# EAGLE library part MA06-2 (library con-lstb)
PIN HEADER
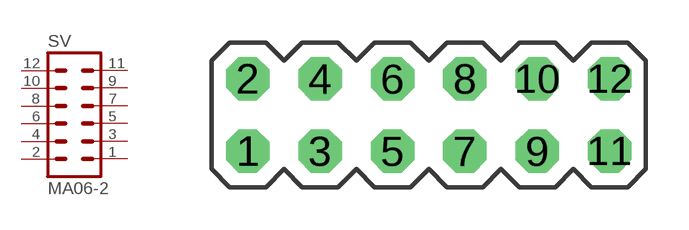
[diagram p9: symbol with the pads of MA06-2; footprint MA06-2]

Designator prefix SV

## MA06-2 (OC_FARNELL: unknown; OC_NEWARK: unknown)  [MA06-2]
1  1  pas
2  2  pas
3  3  pas
4  4  pas
5  5  pas
6  6  pas
7  7  pas
8  8  pas
9  9  pas
10  10  pas
11  11  pas
12  12  pas

## Footprint MA06-2 (pad centres in mm)
PIN HEADER
drill 1.016 octagon: 1 -6.35,-1.27; 2 -6.35,1.27; 3 -3.81,-1.27; 4 -3.81,1.27; 5 -1.27,-1.27; 6 -1.27,1.27; 7 1.27,-1.27; 8 1.27,1.27; 9 3.81,-1.27; 10 3.81,1.27; 11 6.35,-1.27; 12 6.35,1.27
